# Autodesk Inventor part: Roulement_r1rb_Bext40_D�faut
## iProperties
Created: 2011-01
Part Number: Roulement_r1rb_Bext40_D�faut
Document SubType Name: Modeling
Designer: eric
Density: 1 g/cm^3
Mass: 4.29648 g
Surface Area: 35.7935 cm^2
Volume: 4.29648 cm^3
Author: eric
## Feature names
1. Base1
